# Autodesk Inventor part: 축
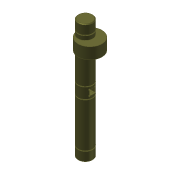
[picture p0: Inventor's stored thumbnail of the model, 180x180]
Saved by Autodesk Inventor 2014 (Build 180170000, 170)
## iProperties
Company: 한국ATC센터
Created: 2015-04
Part Number: 축
Document SubType Name: Modeling
Designer: KYOUNG IL JANG
Density: 7.85 g/cm^3
Material: 강
Mass: 606.905 g
Surface Area: 163.755 cm^2
Volume: 77.3127 cm^3
Appearance: 티타늄
Author: KYOUNG IL JANG
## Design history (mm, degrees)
sketch "스케치1"
  geometry: C1 r 11 at (0, 0); 1 further point
  constraints: 1 centre point, 1 coincident
  dimensions: "d0" = 22 diameter of C1
extrude "돌출1" new body sketch "스케치1" stored distance "d1" = 180; taper "d2" = 0 deg
sketch "스케치2"
  geometry: L1 (-10.247, -4)-(10.247, -4); L2 (-10.247, 4)-(10.247, 4); A1 r 11 centre (0, 0) between (-10.247, -4) and (10.247, -4) reference; 1 further point
  constraints: 4 end point, 4 point on circle, 2 parallel, 1 horizontal
  dimensions: "d3" = 8 distance between parallel lines of L2 L1
extrude "돌출2" cut sketch "스케치2" stored distance "d4" = 8; taper "d5" = 0 deg
sketch "스케치3"
  geometry: 5 further points
hole "구멍1" sketch "스케치3" at (-4, 4), (4, 4), (4, -4), (-4, -4) diameter "d6" = 2; stored, may be unused: countersink angle "d10" = 90 deg, drill point angle "d12" = 118 deg; dims "d7" = 6, "d8" = 4, "d9" = 2, "d11" = 8
chamfer "모따기1" distance "d13" = 1; stored, may be unused: second distance "d14" = 2, angle "d15" = 45 deg
sketch "스케치4"
  geometry: L1 (-10, 9)-(-11, 9); L2 (-11, 9)-(-11, 7.8); L3 (-11, 7.8)-(-10, 7.8); L4 (-10, 7.8)-(-10, 9); L5 (-10, 90)-(10, 90) reference; L6 (0, -15)-(0, 90) reference; L7 (-10, 74.8)-(-11, 74.8); L8 (-11, 74.8)-(-11, 76); L9 (-11, 76)-(-10, 76); L10 (-10, 76)-(-10, 74.8); 1 further point
  constraints: 16 end point, 4 parallel, 2 equal length, 2 horizontal, 2 perpendicular, 1 collinear
  dimensions: "d16" = 7.8 distance from line of L3 point (0, 0); "d17" = 82.2 distance between parallel lines of L3 L5 (derived); "d18" = 11 distance from line of point (0, 0) L2; "d19" = 1 distance of L2.end L3.end; "d20" = 1.2 distance of L1.end L2.end; "d27" = 14 distance between parallel lines of L5 L9
revolve "회전1" sketch "스케치4" stored, may be unused: angle "d21" = 90 deg
sketch "스케치5"
  geometry: L1 (11, 52)-(-7, 52); L2 (-7, 52)-(-7, 69); L3 (-7, 69)-(11, 69); L4 (11, 69)-(11, 52); 1 further point
  constraints: 8 end point, 2 parallel, 1 horizontal, 1 perpendicular
  dimensions: "d22" = 17 distance of L3.end L1.start; "d23" = 36 diameter of L4 L2; "d24" = 7 horizontal distance of L2.end point (0, 0); "d25" = 52 distance from line of L1 point (0, 0)
revolve "회전2" sketch "스케치5" stored, may be unused: angle "d26" = 90 deg
node "솔리드1"
mirror "대칭1"
mirror "대칭2"
